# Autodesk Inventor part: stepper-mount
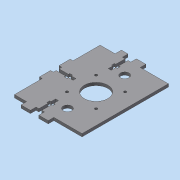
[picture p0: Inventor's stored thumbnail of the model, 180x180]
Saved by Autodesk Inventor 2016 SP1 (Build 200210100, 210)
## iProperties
Created: 2016-06
Part Number: stepper-mount
Material: Generic
Document SubType Name: Modeling
Designer: Mohamed A.
Density: 1 g/cm^3
Appearance: Default
Author: Mohamed A.
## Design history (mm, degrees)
sketch "Sketch1"
  geometry: L1 (-37.5, -49)-(37.5, -49); L2 (37.5, -49)-(37.5, 49); L3 (37.5, 49)-(-37.5, 49); L4 (-37.5, 49)-(-37.5, -49); L5 (-37.5, -49)-(37.5, 49); L6 (37.5, -49)-(-37.5, 49); 1 further point
  constraints: 12 end point, 2 midpoint, 2 parallel, 1 horizontal, 1 perpendicular
  dimensions: "d0" = 75 distance of L2.end L3.end; "d1" = 98 distance of L3.end L1.start
extrude "Extrusion1" new body sketch "Sketch1" distance "d2" = 3; taper "d3" = 0 deg
sketch "Sketch2"
  geometry: L1 (47.5, 46)-(-34.5, 46) reference; L2 (-34.5, -46)-(47.5, -46) reference; L3 (6.5, -46)-(6.5, 46); L4 (-14.5, 21)-(27.5, 21) reference; L5 (27.5, -21)-(-14.5, -21) reference; C1 r 1.5 at (22, -15.5) reference; C2 r 1.5 at (22, 15.5) reference; C3 r 1.5 at (-9, 15.5) reference; C4 r 1.5 at (-9, -15.5) reference; C5 r 12.5 at (6.5, 0) reference; C6 r 1.4 at (-9, -15.5); C7 r 1.4 at (-9, 15.5); C8 r 1.4 at (22, 15.5); C9 r 1.4 at (22, -15.5); C10 r 4.5 at (6.5, 30.5); C11 r 4.5 at (6.5, -30.5); 1 further point
  constraints: 6 centre point, 4 coincident, 3 midpoint, 2 end point, 2 point on line, 1 perpendicular
  dimensions: "d6" = 2.8 diameter of C6; "d7" = 2.8 diameter of C7; "d8" = 2.8 diameter of C8; "d9" = 2.8 diameter of C9; "d10" = 9 diameter of C10; "d13" = 9 diameter of C11; "d16" = 9.5 distance from line of L4 C10.centre (computed from d10); "d17" = 9.5 distance from line of C11.centre L5 (= d16)
extrude "Extrusion2" cut sketch "Sketch2" distance "d4" = 3; taper "d5" = 0 deg
sketch "Sketch3"
  geometry: L1 (-37.5, 49)-(-37.5, -49) reference; L2 (-37.5, 0)-(-11.464, 0); L3 (-37.5, 1.55)-(-16.5, 1.55); L4 (-16.5, 1.55)-(-16.5, -1.55); L5 (-16.5, -1.55)-(-37.5, -1.55); L6 (-37.5, -1.55)-(-37.5, 1.55); L7 (-24.5, 3)-(-21.5, 3); L8 (-21.5, 3)-(-21.5, -3); L9 (-21.5, -3)-(-24.5, -3); L10 (-24.5, -3)-(-24.5, 3); L11 (-37.5, 4.5)-(-34.5, 4.5); L12 (-34.5, 4.5)-(-34.5, -4.5); L13 (-34.5, -4.5)-(-37.5, -4.5); L14 (-37.5, -4.5)-(-37.5, 4.5); L15 (-4.005, 33)-(-10.005, 33); L16 (-10.005, 33)-(-10.005, 36); L17 (-4.005, 36)-(-4.005, 33); L18 (-10.005, 36)-(-4.005, 36); L19 (-7.005, 48.589)-(-7.005, 22.553); L20 (-5.455, 49)-(-5.455, 28); L21 (-8.555, 28)-(-8.555, 49); L22 (-11.505, 46)-(-11.505, 49); L23 (-2.505, 49)-(-2.505, 46); L24 (-2.505, 46)-(-11.505, 46); L25 (-5.455, 28)-(-8.555, 28); L26 (-11.505, 49)-(-2.505, 49); L27 (-8.555, 49)-(-5.455, 49); L28 (37.5, 49)-(-37.5, 49) reference; L29 (-10.005, -33)-(-10.005, -36); L30 (-11.505, -46)-(-11.505, -49); L31 (-8.555, -28)-(-8.555, -49); L32 (-7.005, -48.589)-(-7.005, -22.553); L33 (-5.455, -28)-(-8.555, -28); L34 (-8.555, -49)-(-5.455, -49); L35 (-5.455, -49)-(-5.455, -28); L36 (-4.005, -33)-(-10.005, -33); L37 (-4.005, -36)-(-4.005, -33); L38 (-10.005, -36)-(-4.005, -36); L39 (-2.505, -46)-(-11.505, -46); L40 (-2.505, -49)-(-2.505, -46); L41 (-11.505, -49)-(-2.505, -49); L42 (-37.5, 49)-(-34.5, 49); L43 (-34.5, 49)-(-34.5, 16.333); L44 (-34.5, 16.333)-(-37.5, 16.333); L45 (-37.5, 16.333)-(-37.5, 49); L46 (-37.5, -49)-(-34.5, -49); L47 (-34.5, -49)-(-34.5, -16.333); L48 (-34.5, -16.333)-(-37.5, -16.333); L49 (-37.5, -16.333)-(-37.5, -49); L50 (-34.5, -49)-(-21.505, -49); L51 (-21.505, -49)-(-21.505, -46); L52 (-21.505, -46)-(-34.5, -46); L53 (-34.5, -46)-(-34.5, -49); L54 (-37.5, -49)-(37.5, -49) reference; L55 (37.5, -49)-(7.495, -49); L56 (7.495, -49)-(7.495, -46); L57 (7.495, -46)-(37.5, -46); L58 (37.5, -46)-(37.5, -49); L59 (37.5, 49)-(7.495, 49); L60 (7.495, 49)-(7.495, 46); L61 (7.495, 46)-(37.5, 46); L62 (37.5, 46)-(37.5, 49); L63 (-34.5, 49)-(-18.555, 49); L64 (-18.555, 49)-(-18.555, 45.295)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; 1 further point
  constraints: 126 end point, 24 parallel, 14 symmetric about line, 12 perpendicular, 10 horizontal, 5 point on line, 2 collinear, 1 midpoint, 6 other
  dimensions: "d18" = 21 distance of L4.end L5.end; "d19" = 3.1 distance of L3.end L4.end; "d20" = 3 distance of L8.end L9.end; "d21" = 6 distance of L7.end L8.end; "d22" = 5 distance between parallel lines of L8 L4; "d23" = 3 distance between parallel lines of L14 L12; "d24" = 9 distance between parallel lines of L13 L11; "d25" = 21 distance of L21.start L21.end; "d26" = 3.1 distance of L20.end L21.start; "d27" = 3 distance of L15.end L16.end; "d28" = 6 distance of L15.start L15.end; "d29" = 5 distance between parallel lines of L15 L25; "d30" = 3 distance between parallel lines of L26 L24; "d31" = 9 distance between parallel lines of L22 L23; "d34" = 98 distance between parallel lines of L54 L28 (derived); "d35" = 32.66667 distance between parallel lines of L28 L44 (= 0.333333 x d34); "d36" = 32.66667 distance between parallel lines of L54 L48 (= d35); "d37" = 10 distance between parallel lines of L21 L64; "d38" = 10 distance between parallel lines of L23 L60; "d39" = 10 distance between parallel lines of L51 L30 (= d37); "d40" = 10 distance between parallel lines of L40 L56 (derived)
extrude "Extrusion3" cut sketch "Sketch3" distance "d32" = 3; taper "d33" = 0 deg
sketch "Sketch4"
  geometry: L1 (0, 3)-(0, 0) reference; L2 (0, 0)-(10, 0) reference; L3 (10, 0)-(10, 3) reference; L4 (0, 3)-(10, 3) reference; L5 (-9, 0)-(-9, 3) reference; L6 (-19, 3)-(-9, 3) reference; L7 (-19, 3)-(-19, 0) reference; L8 (-19, 0)-(-9, 0) reference; 1 further point
extrude "Extrusion4" join sketch "Sketch4" distance "d41" = 3; taper "d42" = 0 deg
sketch "Sketch5"
  geometry: L1 (0, 0)-(0, -3) reference; L2 (7.05, -3)-(0, -3) reference; L3 (7.05, -3)-(7.05, 0) reference; L4 (7.05, 0)-(0, 0) reference; L5 (26.05, -3)-(26.05, 0) reference; L6 (26.05, 0)-(16.05, 0) reference; L7 (16.05, 0)-(16.05, -3) reference; L8 (26.05, -3)-(16.05, -3) reference; 1 further point
extrude "Extrusion5" join sketch "Sketch5" distance "d43" = 3; taper "d44" = 0 deg
body "Solid1"
node "Reference1"
node "Reference2"
node "Reference3"
node "Reference4"
node "Reference5"
node "Reference8"
node "Reference9"
node "Reference10"
node "Reference11"
node "Projected Loop1"
node "Projected Loop2"
node "Projected Loop3"
node "Projected Loop4"
